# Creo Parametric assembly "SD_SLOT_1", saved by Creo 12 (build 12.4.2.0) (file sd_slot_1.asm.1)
Units: Custom; MM, KILOGRAM, SECS

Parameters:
  PTC_WM_ITERATION = "0"
  PTC_WM_VERSION = "-.0"
  PTC_WM_LIFECYCLE_STATE = "In Work"
  PTC_WM_LIFECYCLE = "MO_CADDocument"
  PTC_WM_CREATED_BY = "Maximilian Roepper (Z0017RMS: MO)"
  PTC_WM_CREATED_ON = "18-Sep-26 11:36:42 AM"
  PTC_WM_MODIFIED_BY = "Maximilian Roepper (Z0017RMS: MO)"
  PTC_WM_MODIFIED_ON = "18-Sep-26 11:36:46 AM"
  PDMLINKNUMBER = "PDM000071455208"
  PTC_WM_NUMBER = "PDM000071455208"

Other parameters: WEIGHT, WEIGHT_FACTOR, WEIGHT_ADD, MC_ERRORS, SUPPLIER

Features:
  1. coordinate system
  2. imported feature
  3. component "CONTACT01_1"
  4. component "CONTACT02_1"
  5. component "CONTACT03_1"
  6. component "CONTACT04_1"
  7. component "CONTACT05_1"
  8. component "CONTACT06_1"
  9. component "CONTACT07_1"
  10. component "CONTACT08_1"
  11. component "FRAME001_1"
  12. component "CONTACT09_1"
  13. component "COVER_1"
  14. component "CONTACT11_1"
  15. component "CONTACT10_1"

Other named items: DRW_VIEW_ORG, ROUGH-GROB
